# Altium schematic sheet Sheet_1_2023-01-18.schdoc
size 383 x 173 mm
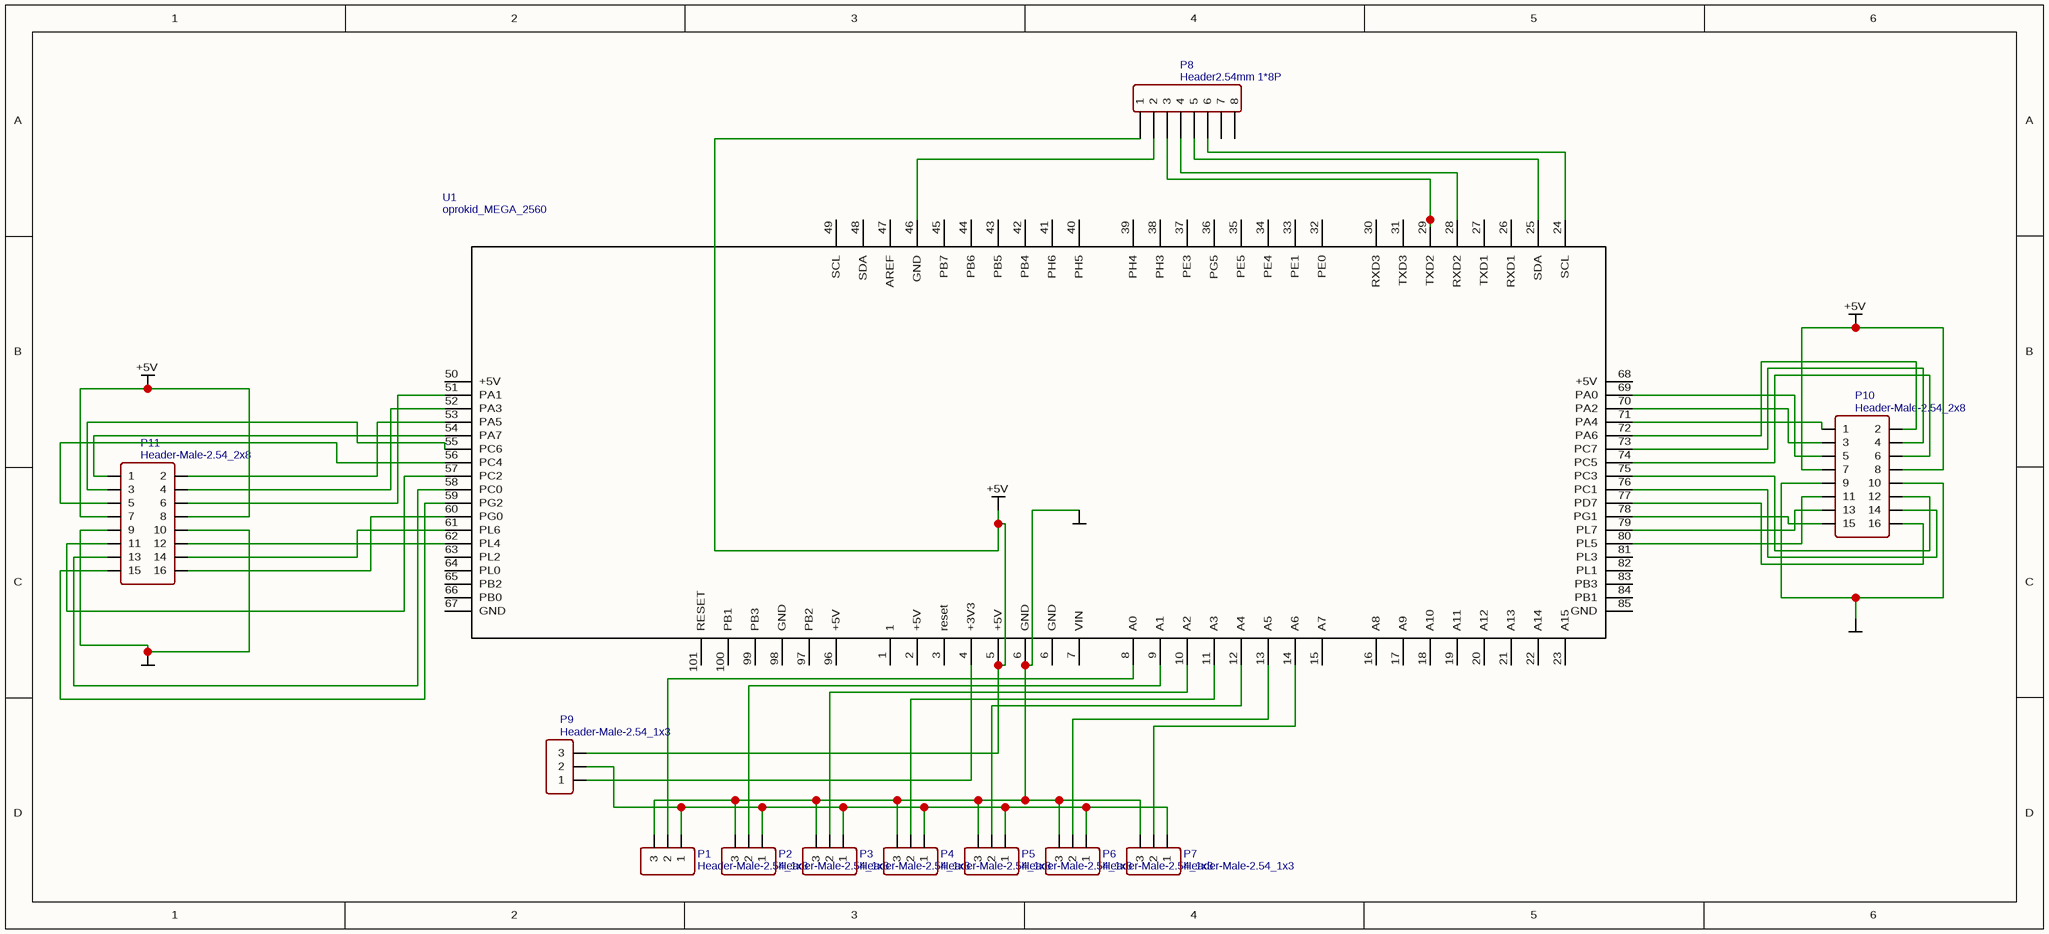
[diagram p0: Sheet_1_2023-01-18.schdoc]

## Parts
P1  Header-Male-2.54_1x3  [HDR-3X1/2.54]
P2  Header-Male-2.54_1x3  [HDR-3X1/2.54]
P3  Header-Male-2.54_1x3  [HDR-3X1/2.54]
P4  Header-Male-2.54_1x3  [HDR-3X1/2.54]
P5  Header-Male-2.54_1x3  [HDR-3X1/2.54]
P6  Header-Male-2.54_1x3  [HDR-3X1/2.54]
P7  Header-Male-2.54_1x3  [HDR-3X1/2.54]
P8  Header2.54mm 1*8P  [HDR-8X1/2.54]
P9  Header-Male-2.54_1x3  [HDR-3X1/2.54]
P10  Header-Male-2.54_2x8  [HDR-8X2/2.54]
P11  Header-Male-2.54_2x8  [HDR-8X2/2.54]
U1  oprokid_MEGA_2560  [KIP_ARDUINO_MEGA_2560]

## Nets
+5V: P8.1 P9.3 P10.7 P10.8 P11.7 P11.8 U1.5(+5V)
GND: P1.3 P2.3 P3.3 P4.3 P5.3 P6.3 P7.3 P10.9 P10.10 P11.9 P11.10 U1.6(GND)
NetP1_1: P1.1 P2.1 P3.1 P4.1 P5.1 P6.1 P7.1 P9.2
NetP1_2: P1.2 U1.8(A0)
NetP2_2: P2.2 U1.9(A1)
NetP3_2: P3.2 U1.10(A2)
NetP4_2: P4.2 U1.11(A3)
NetP5_2: P5.2 U1.12(A4)
NetP6_2: P6.2 U1.13(A5)
NetP7_2: P7.2 U1.14(A6)
NetP8_2: P8.2 U1.46(GND)
NetP8_3: P8.3 U1.29(TXD2)
NetP8_4: P8.4 U1.28(RXD2)
NetP8_5: P8.5 U1.25(SDA)
NetP8_6: P8.6 U1.24(SCL)
NetP9_1: P9.1 U1.4(+3V3)
NetP10_1: P10.1 U1.71(PA4)
NetP10_2: P10.2 U1.72(PA6)
NetP10_3: P10.3 U1.70(PA2)
NetP10_4: P10.4 U1.73(PC7)
NetP10_5: P10.5 U1.69(PA0)
NetP10_6: P10.6 U1.74(PC5)
NetP10_11: P10.11 U1.80(PL5)
NetP10_12: P10.12 U1.75(PC3)
NetP10_13: P10.13 U1.79(PL7)
NetP10_14: P10.14 U1.76(PC1)
NetP10_15: P10.15 U1.78(PG1)
NetP10_16: P10.16 U1.77(PD7)
NetP11_1: P11.1 U1.54(PA7)
NetP11_2: P11.2 U1.53(PA5)
NetP11_3: P11.3 U1.55(PC6)
NetP11_4: P11.4 U1.52(PA3)
NetP11_5: P11.5 U1.56(PC4)
NetP11_6: P11.6 U1.51(PA1)
NetP11_11: P11.11 U1.57(PC2)
NetP11_12: P11.12 U1.62(PL4)
NetP11_13: P11.13 U1.58(PC0)
NetP11_14: P11.14 U1.61(PL6)
NetP11_15: P11.15 U1.59(PG2)
NetP11_16: P11.16 U1.60(PG0)

Not connected (* = marked no-connect by the designer): P8 7 8; U1 1 2(+5V) 3(reset) 7(VIN) 15(A7) 16(A8) 17(A9) 18(A10) 19(A11) 20(A12) 21(A13) 22(A14) 23(A15) 26(RXD1) 27(TXD1) 30(RXD3) 31(TXD3) 32(PE0) 33(PE1) 34(PE4) 35(PE5) 36(PG5) 37(PE3) 38(PH3) 39(PH4) 40(PH5) 41(PH6) 42(PB4) 43(PB5) 44(PB6) 45(PB7) 47(AREF) 48(SDA) 49(SCL) 50(+5V) 63(PL2) 64(PL0) 65(PB2) 66(PB0) 67(GND) 68(+5V) 81(PL3) 82(PL1) 83(PB3) 84(PB1) 85(GND) 96(+5V) 97(PB2) 98(GND) 99(PB3) 100(PB1) 101(RESET)

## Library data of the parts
P1-P7 P9 = Header-Male-2.54_1x3: BOM_Manufacturer: BOOMELE; BOM_Manufacturer Part: Header2.54mm 1*3P
P8 = Header2.54mm 1*8P: BOM_Manufacturer: ReliaPro
P10 P11 = Header-Male-2.54_2x8: BOM_Manufacturer: BOOMELE; BOM_Manufacturer Part: Double row straight 2*8Headers  Pins 2.54mm
U1 = oprokid_MEGA_2560: BOM_Manufacturer Part: Arduino Mega 2560 COMPLETO 2; Contributor: Ivan Ustinov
